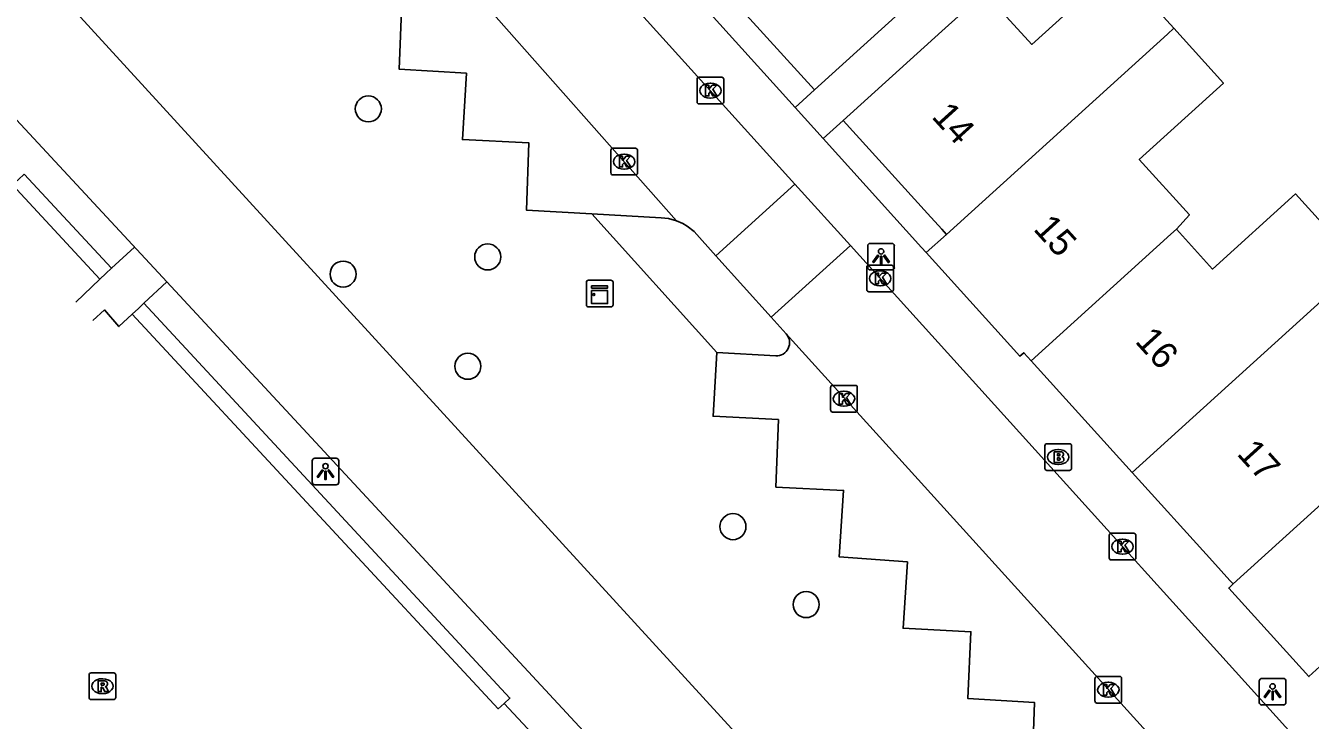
# Model space of a CAD drawing. Extents: x 158352 to 159489, y 383828 to 384597.
# Drawn here: x 159013.24 to 159061.49, y 384122.89 to 384148.96 of the extents above; entities that cross this region are included whole.
import ezdxf

# ---------------------------------------------------------------- set-up
doc = ezdxf.new("R2010")
doc.units = 0
for name, color, linetype in [('IMGEO_Boom', 7, 'Continuous'), ('IMGEO_Brandkraan', 7, 'Continuous'), ('IMGEO_Groenvoorziening', 7, 'Continuous'), ('IMGEO_Haag', 7, 'Continuous'), ('IMGEO_Hek', 7, 'Continuous'), ('IMGEO_Kast', 7, 'Continuous'), ('IMGEO_Kolk', 7, 'Continuous'), ('IMGEO_Lichtpunt', 7, 'Continuous'), ('IMGEO_Pand', 7, 'Continuous'), ('IMGEO_Pand_nummerreeks', 7, 'Continuous'), ('IMGEO_Parkeervlak_open', 7, 'Continuous'), ('IMGEO_Rijbaan_lokaal_open', 7, 'Continuous'), ('IMGEO_Rioolput', 7, 'Continuous'), ('IMGEO_Voetpad_gesloten', 7, 'Continuous'), ('IMGEO_Voetpad_open', 7, 'Continuous')]:
    doc.layers.add(name, color=color, linetype=linetype)

msp = doc.modelspace()

# ---------------------------------------------------------------- linework, layer by layer
at = {"layer": 'IMGEO_Boom'}
for centre in [(159026.112, 384145.834), (159030.595, 384140.277), (159025.165, 384139.633), (159029.85, 384136.173), (159039.807, 384130.154), (159042.557, 384127.229)]:
    msp.add_circle(centre, 0.489, dxfattribs=at)
at = {"layer": 'IMGEO_Brandkraan'}
for p, q in [((159051.521, 384132.341), (159051.521, 384133.193)), ((159051.596, 384133.267), (159052.448, 384133.267)), ((159052.009, 384133.047), (159052.034, 384133.047)), ((159052.522, 384133.193), (159052.522, 384132.341)), ((159052.448, 384132.267), (159051.596, 384132.267)), ((159052.032, 384132.487), (159052.007, 384132.487))]:
    msp.add_line(p, q, dxfattribs=at)
for points in [[(159051.521, 384132.341), (159051.521, 384133.193)], [(159051.596, 384133.267), (159052.448, 384133.267)], [(159052.522, 384133.193), (159052.522, 384132.341)], [(159051.869, 384132.967), (159051.869, 384132.567), (159052.082, 384132.567)], [(159052.1, 384132.967), (159051.869, 384132.967)], [(159052.048, 384132.886), (159051.994, 384132.886), (159051.994, 384132.81)], [(159051.994, 384132.81), (159052.047, 384132.81)], [(159052.056, 384132.734), (159051.994, 384132.734), (159051.994, 384132.653)], [(159051.994, 384132.653), (159052.056, 384132.653)], [(159052.448, 384132.267), (159051.596, 384132.267)]]:
    msp.add_lwpolyline(points, dxfattribs=at)
for centre, radius, start, end in [((159051.598, 384133.191), 0.0765, 91.552, 178.448), ((159051.598, 384133.191), 0.0765, 91.552, 178.448), ((159052.446, 384133.191), 0.0765, 1.552, 88.448), ((159052.446, 384133.191), 0.0765, 1.552, 88.448), ((159052.049, 384132.848), 0.0379, 267.8285, 90.9355), ((159052.057, 384132.693), 0.0404, 269.8759, 90.5077), ((159052.088, 384132.818), 0.251, 268.6676, 293.5347), ((159052.104, 384132.822), 0.145, 59.4692, 91.5367), ((159052.129, 384132.869), 0.0922, 285.5137, 58.1501), ((159052.134, 384132.677), 0.105, 301.3115, 78.989), ((159051.598, 384132.343), 0.0765, 181.552, 268.448), ((159051.598, 384132.343), 0.0765, 181.552, 268.448), ((159052.446, 384132.343), 0.0765, 271.552, 358.448), ((159052.446, 384132.343), 0.0765, 271.552, 358.448)]:
    msp.add_arc(centre, radius, start, end, dxfattribs=at)
for centre, major_axis, ratio, start_param, end_param in [((159052.008, 384132.767), (-0.387, 0.002), 0.722429, 4.712389, 7.853982), ((159052.033, 384132.767), (-0.39, 0.002), 0.717154, 1.570796, 4.712389)]:
    msp.add_ellipse(centre, major_axis=major_axis, ratio=ratio, start_param=start_param, end_param=end_param, dxfattribs=at)
at = {"layer": 'IMGEO_Groenvoorziening'}
for points in [[(159018.539, 384139.342), (159017.685, 384138.543)], [(159031.208, 384123.521), (159032.087, 384122.573), (159035.361, 384119.017)]]:
    msp.add_lwpolyline(points, dxfattribs=at)
at = {"layer": 'IMGEO_Haag'}
for points in [[(159013.192, 384143.387), (159012.971, 384143.183), (159012.752, 384142.979), (159016.029, 384139.446), (159016.255, 384139.658), (159016.469, 384139.854), (159013.192, 384143.387)], [(159017.685, 384138.543), (159017.476, 384138.347), (159017.247, 384138.132), (159030.984, 384123.321), (159031.208, 384123.521)], [(159031.208, 384123.521), (159031.431, 384123.721), (159017.685, 384138.543)]]:
    msp.add_lwpolyline(points, dxfattribs=at)
at = {"layer": 'IMGEO_Hek'}
for points in [[(159017.331, 384140.643), (159016.469, 384139.854)], [(159016.469, 384139.854), (159016.255, 384139.658)], [(159016.029, 384139.446), (159015.124, 384138.585)], [(159016.255, 384139.658), (159016.029, 384139.446)], [(159017.685, 384138.543), (159018.539, 384139.342)], [(159015.765, 384137.894), (159016.197, 384138.289), (159016.745, 384137.662), (159017.247, 384138.132)], [(159017.247, 384138.132), (159017.476, 384138.347)], [(159017.476, 384138.347), (159017.685, 384138.543)]]:
    msp.add_lwpolyline(points, dxfattribs=at)
at = {"layer": 'IMGEO_Kast'}
for p, q in [((159034.304, 384138.476), (159034.304, 384139.317)), ((159034.304, 384139.317), (159034.304, 384138.476)), ((159034.379, 384139.401), (159035.22, 384139.401)), ((159035.22, 384139.401), (159034.379, 384139.401)), ((159035.304, 384139.326), (159035.304, 384138.485)), ((159035.304, 384138.485), (159035.304, 384139.326)), ((159035.229, 384138.401), (159034.388, 384138.401)), ((159034.388, 384138.401), (159035.229, 384138.401))]:
    msp.add_line(p, q, dxfattribs=at)
for points in [[(159034.499, 384139.191), (159035.099, 384139.191), (159035.099, 384139.106), (159034.499, 384139.106), (159034.499, 384139.191)], [(159034.499, 384139.016), (159035.099, 384139.016), (159035.099, 384138.527), (159034.499, 384138.527), (159034.499, 384139.016)]]:
    msp.add_lwpolyline(points, dxfattribs=at)
msp.add_circle((159034.583, 384138.865), 0.0377, dxfattribs=at)
for centre, start, end in [((159034.382, 384139.323), 92.4484, 184.2845), ((159034.382, 384139.323), 92.4484, 184.2845), ((159035.226, 384139.323), 2.4484, 94.2845), ((159035.226, 384139.323), 2.4484, 94.2845), ((159034.382, 384138.479), 182.4484, 274.2845), ((159034.382, 384138.479), 182.4484, 274.2845), ((159035.226, 384138.479), 272.4484, 4.2845), ((159035.226, 384138.479), 272.4484, 4.2845)]:
    msp.add_arc(centre, 0.0779, start, end, dxfattribs=at)
at = {"layer": 'IMGEO_Kolk'}
for p, q in [((159038.532, 384147.021), (159039.384, 384147.021)), ((159038.457, 384146.095), (159038.457, 384146.947)), ((159038.945, 384146.801), (159038.97, 384146.801)), ((159039.458, 384146.947), (159039.458, 384146.095)), ((159039.384, 384146.021), (159038.532, 384146.021)), ((159038.968, 384146.241), (159038.943, 384146.241)), ((159035.22, 384143.428), (159035.22, 384144.28)), ((159035.295, 384144.354), (159036.147, 384144.354)), ((159035.708, 384144.134), (159035.733, 384144.134)), ((159036.221, 384144.28), (159036.221, 384143.428)), ((159036.147, 384143.354), (159035.295, 384143.354)), ((159035.731, 384143.574), (159035.706, 384143.574)), ((159044.833, 384139.045), (159044.833, 384139.897)), ((159044.908, 384139.971), (159045.76, 384139.971)), ((159045.321, 384139.751), (159045.346, 384139.751)), ((159045.834, 384139.897), (159045.834, 384139.045)), ((159045.76, 384138.971), (159044.908, 384138.971)), ((159045.344, 384139.191), (159045.319, 384139.191)), ((159043.551, 384135.457), (159044.403, 384135.457)), ((159043.476, 384134.531), (159043.476, 384135.383)), ((159043.964, 384135.237), (159043.989, 384135.237)), ((159044.477, 384135.383), (159044.477, 384134.531)), ((159044.403, 384134.457), (159043.551, 384134.457)), ((159043.987, 384134.677), (159043.962, 384134.677)), ((159053.938, 384128.979), (159053.938, 384129.831)), ((159054.013, 384129.905), (159054.865, 384129.905)), ((159054.426, 384129.685), (159054.451, 384129.685)), ((159054.939, 384129.831), (159054.939, 384128.979)), ((159054.449, 384129.125), (159054.424, 384129.125)), ((159054.865, 384128.905), (159054.013, 384128.905)), ((159053.404, 384123.605), (159053.404, 384124.457)), ((159053.479, 384124.531), (159054.331, 384124.531)), ((159053.892, 384124.311), (159053.917, 384124.311)), ((159054.405, 384124.457), (159054.405, 384123.605)), ((159054.331, 384123.531), (159053.479, 384123.531)), ((159053.915, 384123.751), (159053.89, 384123.751))]:
    msp.add_line(p, q, dxfattribs=at)
for points in [[(159038.532, 384147.021), (159039.384, 384147.021)], [(159038.457, 384146.095), (159038.457, 384146.947)], [(159038.778, 384146.721), (159038.901, 384146.721), (159038.901, 384146.57), (159039.031, 384146.721), (159039.195, 384146.721), (159039.049, 384146.57), (159039.202, 384146.321), (159039.05, 384146.321), (159038.965, 384146.485), (159038.901, 384146.418), (159038.901, 384146.321), (159038.778, 384146.321), (159038.778, 384146.721)], [(159039.458, 384146.947), (159039.458, 384146.095)], [(159039.384, 384146.021), (159038.532, 384146.021)], [(159035.22, 384143.428), (159035.22, 384144.28)], [(159035.295, 384144.354), (159036.147, 384144.354)], [(159036.221, 384144.28), (159036.221, 384143.428)], [(159035.541, 384144.054), (159035.664, 384144.054), (159035.664, 384143.903), (159035.794, 384144.054), (159035.958, 384144.054), (159035.812, 384143.903), (159035.965, 384143.654), (159035.813, 384143.654), (159035.728, 384143.818), (159035.664, 384143.751), (159035.664, 384143.654), (159035.541, 384143.654), (159035.541, 384144.054)], [(159036.147, 384143.354), (159035.295, 384143.354)], [(159044.833, 384139.045), (159044.833, 384139.897)], [(159044.908, 384139.971), (159045.76, 384139.971)], [(159045.834, 384139.897), (159045.834, 384139.045)], [(159045.154, 384139.671), (159045.277, 384139.671), (159045.277, 384139.52), (159045.407, 384139.671), (159045.571, 384139.671), (159045.425, 384139.52), (159045.578, 384139.271), (159045.426, 384139.271), (159045.341, 384139.435), (159045.277, 384139.368), (159045.277, 384139.271), (159045.154, 384139.271), (159045.154, 384139.671)], [(159045.76, 384138.971), (159044.908, 384138.971)], [(159043.551, 384135.457), (159044.403, 384135.457)], [(159043.476, 384134.531), (159043.476, 384135.383)], [(159043.797, 384135.157), (159043.92, 384135.157), (159043.92, 384135.006), (159044.05, 384135.157), (159044.214, 384135.157), (159044.068, 384135.006), (159044.221, 384134.757), (159044.069, 384134.757), (159043.984, 384134.921), (159043.92, 384134.854), (159043.92, 384134.757), (159043.797, 384134.757), (159043.797, 384135.157)], [(159044.477, 384135.383), (159044.477, 384134.531)], [(159044.403, 384134.457), (159043.551, 384134.457)], [(159053.938, 384128.979), (159053.938, 384129.831)], [(159054.013, 384129.905), (159054.865, 384129.905)], [(159054.259, 384129.605), (159054.382, 384129.605), (159054.382, 384129.454), (159054.512, 384129.605), (159054.676, 384129.605), (159054.53, 384129.454), (159054.683, 384129.205), (159054.531, 384129.205), (159054.446, 384129.369), (159054.382, 384129.302), (159054.382, 384129.205), (159054.259, 384129.205), (159054.259, 384129.605)], [(159054.939, 384129.831), (159054.939, 384128.979)], [(159054.865, 384128.905), (159054.013, 384128.905)], [(159053.404, 384123.605), (159053.404, 384124.457)], [(159053.479, 384124.531), (159054.331, 384124.531)], [(159054.405, 384124.457), (159054.405, 384123.605)], [(159053.725, 384124.231), (159053.848, 384124.231), (159053.848, 384124.08), (159053.978, 384124.231), (159054.142, 384124.231), (159053.996, 384124.08), (159054.149, 384123.831), (159053.997, 384123.831), (159053.912, 384123.995), (159053.848, 384123.928), (159053.848, 384123.831), (159053.725, 384123.831), (159053.725, 384124.231)], [(159054.331, 384123.531), (159053.479, 384123.531)]]:
    msp.add_lwpolyline(points, dxfattribs=at)
for centre, start, end in [((159038.534, 384146.945), 91.552, 178.448), ((159038.534, 384146.945), 91.552, 178.448), ((159039.382, 384146.945), 1.552, 88.448), ((159039.382, 384146.945), 1.552, 88.448), ((159038.534, 384146.097), 181.552, 268.448), ((159038.534, 384146.097), 181.552, 268.448), ((159039.382, 384146.097), 271.552, 358.448), ((159039.382, 384146.097), 271.552, 358.448), ((159035.297, 384144.278), 91.552, 178.448), ((159035.297, 384144.278), 91.552, 178.448), ((159036.145, 384144.278), 1.552, 88.448), ((159036.145, 384144.278), 1.552, 88.448), ((159035.297, 384143.43), 181.552, 268.448), ((159035.297, 384143.43), 181.552, 268.448), ((159036.145, 384143.43), 271.552, 358.448), ((159036.145, 384143.43), 271.552, 358.448), ((159044.91, 384139.895), 91.552, 178.448), ((159044.91, 384139.895), 91.552, 178.448), ((159045.758, 384139.895), 1.552, 88.448), ((159045.758, 384139.895), 1.552, 88.448), ((159044.91, 384139.047), 181.552, 268.448), ((159044.91, 384139.047), 181.552, 268.448), ((159045.758, 384139.047), 271.552, 358.448), ((159045.758, 384139.047), 271.552, 358.448), ((159043.553, 384135.381), 91.552, 178.448), ((159043.553, 384135.381), 91.552, 178.448), ((159044.401, 384135.381), 1.552, 88.448), ((159044.401, 384135.381), 1.552, 88.448), ((159043.553, 384134.533), 181.552, 268.448), ((159043.553, 384134.533), 181.552, 268.448), ((159044.401, 384134.533), 271.552, 358.448), ((159044.401, 384134.533), 271.552, 358.448), ((159054.015, 384129.829), 91.552, 178.448), ((159054.015, 384129.829), 91.552, 178.448), ((159054.863, 384129.829), 1.552, 88.448), ((159054.863, 384129.829), 1.552, 88.448), ((159054.015, 384128.981), 181.552, 268.448), ((159054.015, 384128.981), 181.552, 268.448), ((159054.863, 384128.981), 271.552, 358.448), ((159054.863, 384128.981), 271.552, 358.448), ((159053.481, 384124.455), 91.552, 178.448), ((159053.481, 384124.455), 91.552, 178.448), ((159054.329, 384124.455), 1.552, 88.448), ((159054.329, 384124.455), 1.552, 88.448), ((159053.481, 384123.607), 181.552, 268.448), ((159053.481, 384123.607), 181.552, 268.448), ((159054.329, 384123.607), 271.552, 358.448), ((159054.329, 384123.607), 271.552, 358.448)]:
    msp.add_arc(centre, 0.0765, start, end, dxfattribs=at)
for centre, major_axis, ratio, start_param, end_param in [((159038.944, 384146.521), (-0.387, 0.002), 0.722429, 4.712389, 7.853982), ((159038.969, 384146.521), (-0.39, 0.002), 0.717154, 1.570796, 4.712389), ((159035.707, 384143.854), (-0.387, 0.002), 0.722429, 4.712389, 7.853982), ((159035.732, 384143.854), (-0.39, 0.002), 0.717154, 1.570796, 4.712389), ((159045.32, 384139.471), (-0.387, 0.002), 0.722429, 4.712389, 7.853982), ((159045.345, 384139.471), (-0.39, 0.002), 0.717154, 1.570796, 4.712389), ((159043.963, 384134.957), (-0.387, 0.002), 0.722429, 4.712389, 7.853982), ((159043.988, 384134.957), (-0.39, 0.002), 0.717154, 1.570796, 4.712389), ((159054.425, 384129.405), (-0.387, 0.002), 0.722429, 4.712389, 7.853982), ((159054.45, 384129.405), (-0.39, 0.002), 0.717154, 1.570796, 4.712389), ((159053.891, 384124.031), (-0.387, 0.002), 0.722429, 4.712389, 7.853982), ((159053.916, 384124.031), (-0.39, 0.002), 0.717154, 1.570796, 4.712389)]:
    msp.add_ellipse(centre, major_axis=major_axis, ratio=ratio, start_param=start_param, end_param=end_param, dxfattribs=at)
at = {"layer": 'IMGEO_Lichtpunt'}
for p, q in [((159045.773, 384140.784), (159044.965, 384140.784)), ((159045.773, 384140.784), (159044.965, 384140.784)), ((159044.871, 384140.689), (159044.871, 384139.882)), ((159044.871, 384140.689), (159044.871, 384139.882)), ((159045.867, 384139.882), (159045.867, 384140.689)), ((159045.867, 384139.882), (159045.867, 384140.689)), ((159044.965, 384139.788), (159045.773, 384139.788)), ((159044.965, 384139.788), (159045.773, 384139.788)), ((159024.004, 384132.626), (159024.004, 384131.819)), ((159024.004, 384132.626), (159024.004, 384131.819)), ((159024.906, 384132.721), (159024.098, 384132.721)), ((159024.906, 384132.721), (159024.098, 384132.721)), ((159025, 384131.819), (159025, 384132.626)), ((159025, 384131.819), (159025, 384132.626)), ((159024.098, 384131.725), (159024.906, 384131.725)), ((159024.098, 384131.725), (159024.906, 384131.725)), ((159059.576, 384124.361), (159059.576, 384123.554)), ((159059.576, 384124.361), (159059.576, 384123.554)), ((159060.478, 384124.456), (159059.67, 384124.456)), ((159060.478, 384124.456), (159059.67, 384124.456)), ((159060.572, 384123.554), (159060.572, 384124.361)), ((159060.572, 384123.554), (159060.572, 384124.361)), ((159059.67, 384123.46), (159060.478, 384123.46)), ((159059.67, 384123.46), (159060.478, 384123.46))]:
    msp.add_line(p, q, dxfattribs=at)
for points in [[(159045.245, 384140.353), (159045.284, 384140.325), (159045.096, 384140.063), (159045.058, 384140.09), (159045.245, 384140.353)], [(159045.347, 384140.305), (159045.394, 384140.305), (159045.394, 384139.983), (159045.347, 384139.983), (159045.347, 384140.305)], [(159045.457, 384140.325), (159045.495, 384140.352), (159045.682, 384140.09), (159045.643, 384140.062), (159045.457, 384140.325)], [(159024.378, 384132.29), (159024.417, 384132.262), (159024.229, 384132), (159024.191, 384132.027), (159024.378, 384132.29)], [(159024.48, 384132.242), (159024.527, 384132.242), (159024.527, 384131.92), (159024.48, 384131.92), (159024.48, 384132.242)], [(159024.59, 384132.262), (159024.628, 384132.289), (159024.815, 384132.027), (159024.776, 384131.999), (159024.59, 384132.262)], [(159059.95, 384124.025), (159059.989, 384123.997), (159059.801, 384123.735), (159059.763, 384123.762), (159059.95, 384124.025)], [(159060.052, 384123.977), (159060.099, 384123.977), (159060.099, 384123.655), (159060.052, 384123.655), (159060.052, 384123.977)], [(159060.162, 384123.997), (159060.2, 384124.024), (159060.387, 384123.762), (159060.348, 384123.734), (159060.162, 384123.997)]]:
    msp.add_lwpolyline(points, dxfattribs=at)
for centre in [(159045.37, 384140.487), (159024.503, 384132.424), (159060.075, 384124.159)]:
    msp.add_circle(centre, 0.0994, dxfattribs=at)
for centre, start, end in [((159044.965, 384140.689), 90, 180), ((159044.965, 384140.689), 90, 180), ((159045.773, 384140.689), 0, 90), ((159045.773, 384140.689), 0, 90), ((159044.965, 384139.882), 180, 270), ((159044.965, 384139.882), 180, 270), ((159045.773, 384139.882), 270, 0), ((159045.773, 384139.882), 270, 360), ((159024.098, 384132.626), 90, 180), ((159024.098, 384132.626), 90, 180), ((159024.906, 384132.626), 0, 90), ((159024.906, 384132.626), 0, 90), ((159024.098, 384131.819), 180, 270), ((159024.098, 384131.819), 180, 270), ((159024.906, 384131.819), 270, 0), ((159024.906, 384131.819), 270, 360), ((159059.67, 384124.361), 90, 180), ((159059.67, 384124.361), 90, 180), ((159060.478, 384124.361), 0, 90), ((159060.478, 384124.361), 0, 90), ((159059.67, 384123.554), 180, 270), ((159059.67, 384123.554), 180, 270), ((159060.478, 384123.554), 270, 0), ((159060.478, 384123.554), 270, 360)]:
    msp.add_arc(centre, 0.0946, start, end, dxfattribs=at)
at = {"layer": 'IMGEO_Pand'}
for points in [[(159048.22, 384151.389), (159046.573, 384149.901), (159042.867, 384146.544)], [(159049.259, 384150.207), (159051.029, 384148.253), (159054.26, 384151.18), (159056.363, 384148.858)], [(159039.165, 384150.631), (159042.867, 384146.544)], [(159043.949, 384145.398), (159047.656, 384148.755), (159049.259, 384150.207)], [(159047.823, 384141.122), (159056.124, 384148.641), (159056.363, 384148.858)], [(159056.363, 384148.858), (159058.228, 384146.798), (159055.068, 384143.936), (159056.948, 384141.86), (159056.462, 384141.322)], [(159043.949, 384145.398), (159047.108, 384141.911), (159047.646, 384141.317), (159047.823, 384141.122)], [(159056.462, 384141.322), (159057.822, 384139.82), (159060.939, 384142.644), (159063.373, 384139.957)], [(159051.006, 384136.38), (159056.247, 384141.128), (159056.462, 384141.322)], [(159047.823, 384141.122), (159047.068, 384140.438)], [(159051.006, 384136.38), (159050.732, 384136.683), (159050.587, 384136.552), (159047.068, 384140.438)], [(159063.373, 384139.957), (159054.8, 384132.191)], [(159054.8, 384132.191), (159051.006, 384136.38)], [(159058.594, 384128.003), (159064.303, 384133.174), (159064.533, 384133.383)], [(159058.594, 384128.003), (159058.473, 384128.136), (159057.822, 384128.855), (159054.8, 384132.191)], [(159062.912, 384124.289), (159062.127, 384125.155), (159061.436, 384124.528), (159058.426, 384127.851), (159058.594, 384128.003)]]:
    msp.add_lwpolyline(points, dxfattribs=at)
at = {"layer": 'IMGEO_Parkeervlak_open'}
for points in [[(159034.505, 384141.891), (159032.056, 384142.027), (159032.143, 384144.559), (159029.646, 384144.683), (159029.794, 384147.169), (159027.27, 384147.326), (159027.369, 384149.835), (159024.891, 384149.991), (159024.988, 384152.479), (159022.486, 384152.619), (159022.589, 384155.154), (159020.098, 384155.319), (159020.199, 384157.722)], [(159053.394, 384120.931), (159051.046, 384121.062), (159051.127, 384123.555), (159048.63, 384123.703), (159048.742, 384126.212), (159046.196, 384126.338), (159046.36, 384128.831), (159043.798, 384129.019), (159043.962, 384131.512), (159041.417, 384131.637), (159041.515, 384134.173), (159039.063, 384134.297), (159039.2, 384136.685)]]:
    msp.add_lwpolyline(points, dxfattribs=at)
at = {"layer": 'IMGEO_Rijbaan_lokaal_open'}
for points in [[(159023.125, 384164.023), (159042.135, 384143.006)], [(159037.685, 384141.635), (159022.793, 384158.457)], [(159042.135, 384143.006), (159039.169, 384140.322)], [(159042.135, 384143.006), (159044.215, 384140.706)], [(159039.169, 384140.322), (159038.351, 384141.233), (159038.089, 384141.432), (159037.922, 384141.528), (159037.685, 384141.635)], [(159044.215, 384140.706), (159041.241, 384138.016)], [(159065.968, 384116.658), (159044.215, 384140.706)], [(159041.241, 384138.016), (159039.169, 384140.322)], [(159041.241, 384138.016), (159041.806, 384137.388)], [(159041.806, 384137.388), (159057.024, 384120.599)]]:
    msp.add_lwpolyline(points, dxfattribs=at)
at = {"layer": 'IMGEO_Rioolput'}
for p, q in [((159015.623, 384123.739), (159015.623, 384124.591)), ((159015.698, 384124.665), (159016.55, 384124.665)), ((159016.111, 384124.445), (159016.136, 384124.445)), ((159016.624, 384124.591), (159016.624, 384123.739)), ((159016.134, 384123.885), (159016.109, 384123.885)), ((159016.55, 384123.665), (159015.698, 384123.665))]:
    msp.add_line(p, q, dxfattribs=at)
for points in [[(159015.623, 384123.739), (159015.623, 384124.591)], [(159015.698, 384124.665), (159016.55, 384124.665)], [(159016.212, 384124.363), (159015.96, 384124.365), (159015.96, 384123.965)], [(159016.624, 384124.591), (159016.624, 384123.739)], [(159015.96, 384123.965), (159016.084, 384123.965), (159016.084, 384124.127), (159016.095, 384124.127)], [(159016.138, 384124.284), (159016.084, 384124.284), (159016.084, 384124.203)], [(159016.084, 384124.203), (159016.136, 384124.203)], [(159016.142, 384124.098), (159016.213, 384123.965), (159016.353, 384123.965), (159016.288, 384124.091)], [(159016.55, 384123.665), (159015.698, 384123.665)]]:
    msp.add_lwpolyline(points, dxfattribs=at)
for centre, radius, start, end in [((159015.7, 384124.589), 0.0765, 91.552, 178.448), ((159015.7, 384124.589), 0.0765, 91.552, 178.448), ((159016.211, 384124.253), 0.109, 350.3612, 89.416), ((159016.548, 384124.589), 0.0765, 1.552, 88.448), ((159016.548, 384124.589), 0.0765, 1.552, 88.448), ((159016.094, 384124.074), 0.0533, 26.0293, 88.6989), ((159016.12, 384124.392), 0.19, 274.7715, 282.9687), ((159016.144, 384124.188), 0.0964, 77.0061, 93.1865), ((159016.158, 384124.245), 0.0378, 276.6634, 79.6772), ((159016.209, 384124.253), 0.112, 277.5842, 350.9817), ((159016.193, 384124.038), 0.108, 29.5134, 73.7905), ((159015.7, 384123.741), 0.0765, 181.552, 268.448), ((159015.7, 384123.741), 0.0765, 181.552, 268.448), ((159016.548, 384123.741), 0.0765, 271.552, 358.448), ((159016.548, 384123.741), 0.0765, 271.552, 358.448)]:
    msp.add_arc(centre, radius, start, end, dxfattribs=at)
for centre, major_axis, ratio, start_param, end_param in [((159016.11, 384124.165), (-0.387, 0.002), 0.722429, 4.712389, 7.853982), ((159016.135, 384124.165), (-0.39, 0.002), 0.717154, 1.570796, 4.712389)]:
    msp.add_ellipse(centre, major_axis=major_axis, ratio=ratio, start_param=start_param, end_param=end_param, dxfattribs=at)
at = {"layer": 'IMGEO_Voetpad_gesloten'}
for points in [[(159016.111, 384157.258), (159011.775, 384153.125), (159044.617, 384117.262)], [(159008.198, 384150.484), (159018.539, 384139.342)], [(159042.658, 384113.356), (159018.539, 384139.342)]]:
    msp.add_lwpolyline(points, dxfattribs=at)
at = {"layer": 'IMGEO_Voetpad_open'}
for points in [[(159042.141, 384145.887), (159027.515, 384162.065)], [(159042.867, 384146.544), (159042.141, 384145.887)], [(159042.141, 384145.887), (159043.197, 384144.719)], [(159043.197, 384144.719), (159043.949, 384145.398)], [(159047.068, 384140.438), (159046.891, 384140.633), (159043.197, 384144.719)], [(159037.685, 384141.635), (159037.382, 384141.718), (159037.11, 384141.746), (159034.505, 384141.891)], [(159039.2, 384136.685), (159034.505, 384141.891)], [(159039.2, 384136.685), (159041.411, 384136.563)]]:
    msp.add_lwpolyline(points, dxfattribs=at)
msp.add_arc((159041.437, 384137.058), 0.495, 266.9696, 41.8613, dxfattribs=at)

# ---------------------------------------------------------------- texts
at = {"layer": 'IMGEO_Pand_nummerreeks'}
for s, rotation, p in [('14', 312.1752, (159047.233, 384145.526)), ('15', 312.1752, (159051.054, 384141.308)), ('16', 312.1736, (159054.875, 384137.09)), ('17', 312.1752, (159058.696, 384132.872))]:
    msp.add_text(s, height=1, rotation=rotation, dxfattribs=at).set_placement(p)

doc.saveas('drawing.dxf')
